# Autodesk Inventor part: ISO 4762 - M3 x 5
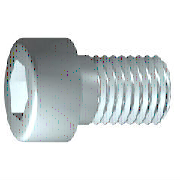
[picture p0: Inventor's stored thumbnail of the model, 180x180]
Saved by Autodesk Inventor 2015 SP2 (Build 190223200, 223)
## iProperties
Created: 2012-02
Part Number: ISO 4762 - M3 x 5
Material: Edelstahl, 440C
Description: Innensechskantschraube
Document SubType Name: Modeling
Standard: ISO 4762
Designer: rYan
Standard Revision: 1998
Standards Organization: DIN
Language: de-DE
Size Designation: M3 x 5
Categories: <MemberInstance><Categories><Category DisplayName="Verbindungselemente" InternalName="e4da775c-781d-43d5-af7c-5136215cf5a6" Mnemonic="FSTN"><Category DisplayNam
Density: 7.75 g/cm^3
Appearance: Halbpoliert
IsCustomPart: 0
Author: rYan
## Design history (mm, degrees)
sketch "Skizze1"
  geometry: L1 (-0.867, 0)-(5, 0); L2 (5, 0)-(5, 1.5); L3 (5, 1.5)-(1.25, 1.5); L4 (1.25, 1.5)-(0.943, 1.5); L5 (0.943, 1.5)-(0, 1.5); L6 (0, 1.5)-(0, 2.75); L7 (0, 2.75)-(-3, 2.75); L8 (-3, 2.75)-(-3, 1.443); L9 (-3, 1.443)-(-1.7, 1.443); L10 (-1.7, 1.443)-(-0.867, 0); L11 (-4.6, 0)-(6.6, 0) reference; L12 (0, -0.55)-(0, 3.3) reference; L13 (1.25, 1.5)-(0, 1.5)
  constraints: 22 end point, 6 parallel, 2 collinear, 2 perpendicular, 1 horizontal, 1 point on line
  dimensions: "d1" = 3.75 distance from line of L3.end L2 (= GEL); "d2" = 0.30683 distance of L4.end L3.end (computed from GAL); "d3" = 3 distance between parallel lines of L8 L6 (= KOH); "d4" = 1.3 distance of L8.end L9.end (= INTI); "d5" = 60 deg angle of L10 L1; "d6" = 3 diameter of L3 L1 (= GD); "d7" = 3 diameter of L5 L1 (= BDM); "d8" = 2.88675 diameter of L9 L1 (= 1.1547 x SW); "d9" = 5.5 diameter of L7 L1 (= KOD); "d26" = 5 distance between parallel lines of L12 L2 (= NLG)
revolve "Körper" sketch "Skizze1" stored, may be unused: angle "d10" = 90 deg
sketch "Skizze2"
  geometry: L1 (0, -3.85)-(0, 3.85) reference; L2 (-3.85, 0)-(3.85, 0) reference; L3 (1.443, 0)-(0.722, -1.25); L4 (0.722, -1.25)-(-0.722, -1.25); L5 (-0.722, -1.25)-(-1.443, 0); L6 (-1.443, 0)-(-0.722, 1.25); L7 (-0.722, 1.25)-(0.722, 1.25); L8 (0.722, 1.25)-(1.443, 0); 2 further points
  constraints: 12 end point, 1 coincident, 1 horizontal alignment, 1 point on line, 12 other
extrude "Loch" join sketch "Skizze2" stored distance "d11" = 10; taper "d12" = 0 deg
workplane "Work Plane1"
fillet "Fillet2" dims "d30" = 0.1 (= R)
body "Solid1"
fillet "Rundung1" dims "d17" = 0.3 (= RR)
feature "Gewinde" dims "d13" = 3.75 (= GEL), "d14" = 0
chamfer "Fase1" distance "d15" = 0.30673 (= -0.5 x SPD + 0.5 x GD); stored, may be unused: second distance "d16" = 0.30673 (= GUL), angle "d27" = 45 deg
other parameters: "GD" = 3 [user parameter; used in 2 equation terms], "NLG" = 5 [user parameter; used in 1 equation term], "GEL" = 3.75 [user parameter; used in 2 equation terms], "KOD" = 5.5 [user parameter; used in 1 equation term], "KOH" = 3 [user parameter; used in 1 equation term], "INTI" = 1.3 [user parameter; used in 1 equation term], "GAL" = 0.30673 (= 0.61345 x PTC) [user parameter; used in 1 equation term], "GUL" = 0.30673 (= 0.61345 x PTC) [user parameter; used in 1 equation term], "BDM" = 3 (= NND) [user parameter; used in 1 equation term], "SW" = 2.5 [user parameter; used in 2 equation terms], "RR" = 0.3 [user parameter; used in 1 equation term], "SPD" = 2.38655 (= NND - 1.2269 x PTC) [user parameter; used in 1 equation term], "d19" = 0, "d28" = 0, "d29" = 0, "R" = 0.1 [user parameter; used in 1 equation term], "TOA" = 30 deg [user parameter], "GD1" = 2.38655 (= THREADDIA - 1.2269 x PTC) [user parameter], "THREADDIA" = 3 [user parameter; used in 1 equation term], "FAWI" = 45 deg [user parameter], "PTC" = 0.5 [user parameter; used in 5 equation terms], "NND" = 3 [user parameter; used in 2 equation terms], "E0" = 2.8875 (= 1.155 x SW) [user parameter]
